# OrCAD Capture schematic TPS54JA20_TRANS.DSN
size E; title: TPS54JA20 2.7-V to 16-V Input, 12-A Synchronous Step-down; rev: 1.0; note: Datasheet:SNVSB02     EVM:NA; note: Synchronous Step Down Converter
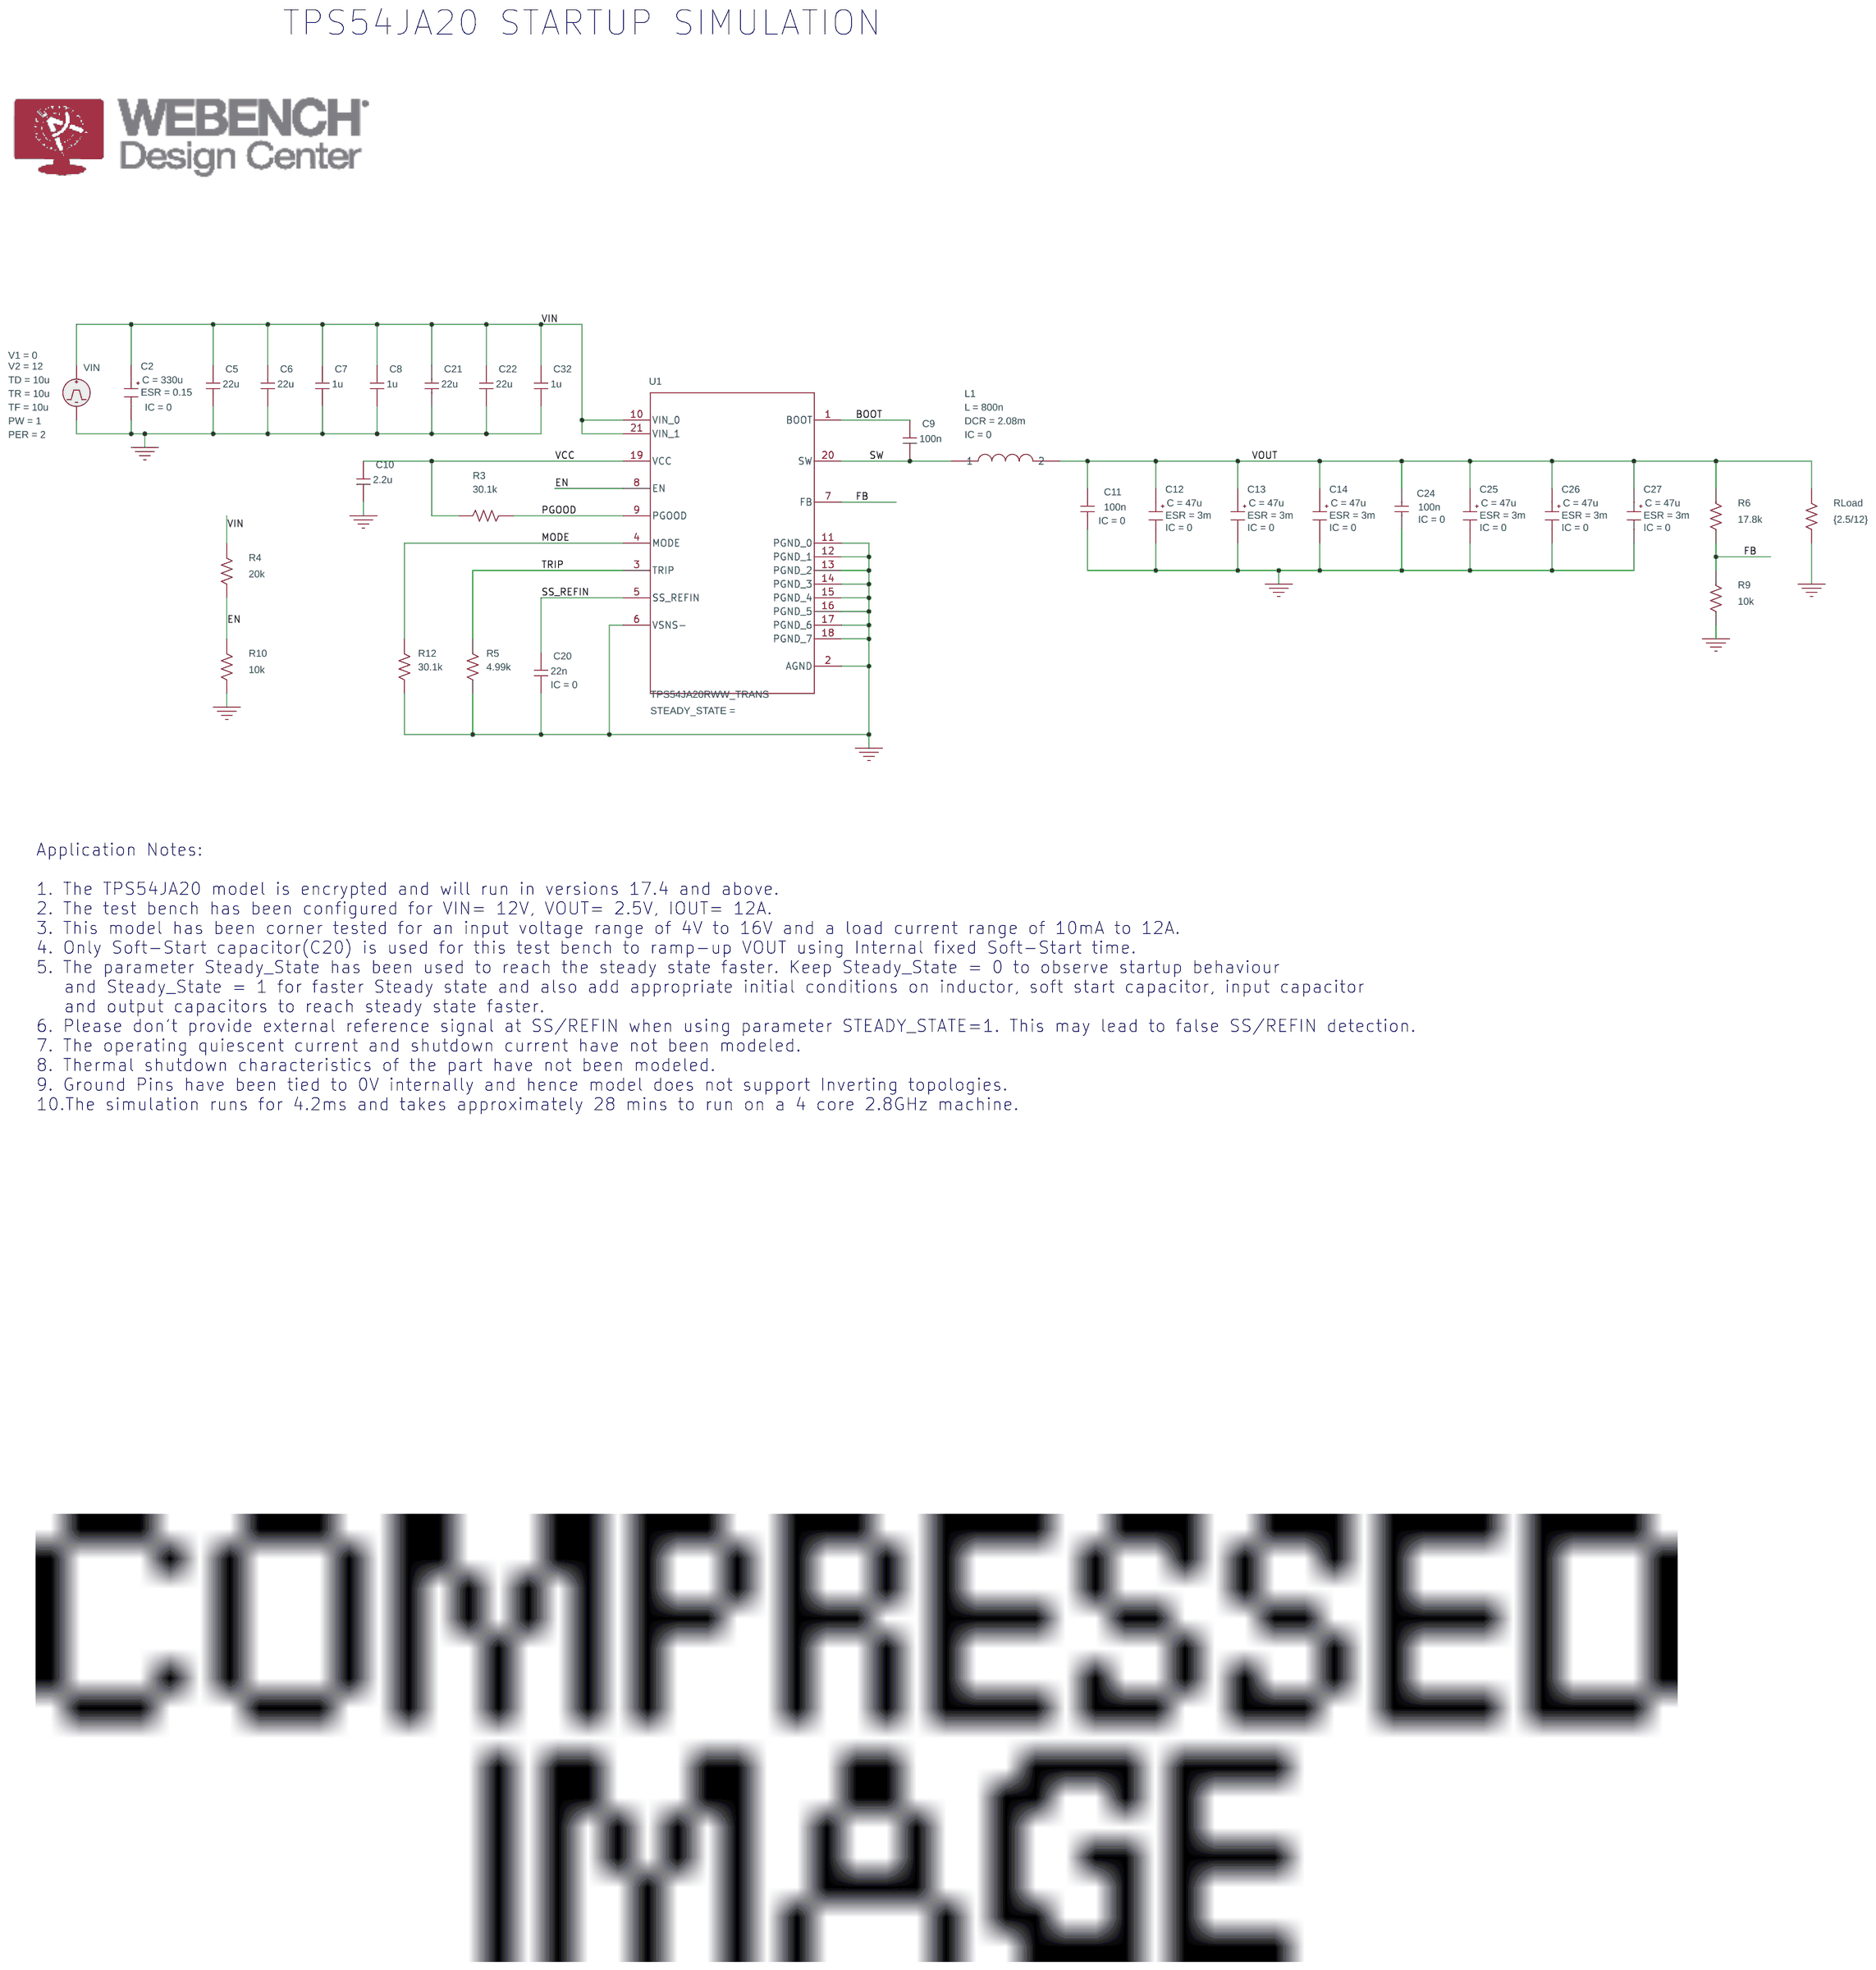
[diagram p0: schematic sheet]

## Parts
C2  CESR
C5  22u  [RAD/CK05]
C6  22u  [RAD/CK05]
C7  1u  [RAD/CK05]
C8  1u  [RAD/CK05]
C9  100n  [RAD/CK05]
C10  2.2u  [RAD/CK05]
C11  100n  [RAD/CK05]
C12  CESR
C13  CESR
C14  CESR
C20  22n  [RAD/CK05]
C21  22u  [RAD/CK05]
C22  22u  [RAD/CK05]
C24  100n  [RAD/CK05]
C25  CESR
C26  CESR
C27  CESR
C32  1u  [RAD/CK05]
L1  LDCR
R3  30.1k  [AX/RC05]
R4  20k  [AX/RC05]
R5  4.99k  [AX/RC05]
R6  17.8k  [AX/RC05]
R9  10k  [AX/RC05]
R10  10k  [AX/RC05]
R12  30.1k  [AX/RC05]
RLoad  {2.5/12}  [AX/RC05]
U1  TPS54JA20RWW_TRANS  [RWW0021A]
VIN  VPULSE

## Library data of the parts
C2 = CESR_0: C: 330u; ESR: 0.15; IC: 0; PSpiceTemplate: X^@REFDES %IN %OUT @MODEL PARAMS:  ?C|C=@C||C=100u|  ?ESR|ESR=@ESR||ESR=0.01| ?X|X=@X||X=2|  ?IC|IC=@IC||IC=2|; X: 1
C5-C10 C21 C22 C32 = c_0
C11 C20 C24 = c_0: IC: 0
C12-C14 C25-C27 = CESR_0: C: 47u; ESR: 3m; IC: 0; PSpiceTemplate: X^@REFDES %IN %OUT @MODEL PARAMS:  ?C|C=@C||C=100u|  ?ESR|ESR=@ESR||ESR=0.01| ?X|X=@X||X=2|  ?IC|IC=@IC||IC=2|; X: 1
L1 = LDCR: DCR: 2.08m; IC: 0; L: 800n
R3-R6 R9 R10 R12 RLoad = R
U1 = TPS54JA20RWW_TRANS
VIN = VPULSE: PER: 2; PW: 1; TD: 10u; TF: 10u; TR: 10u; V1: 0; V2: 12

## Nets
VCC: C10.1 R3.2 U1.19(VCC)
VIN: C2.1(IN) C5.1 C6.1 C7.1 C8.1 C21.1 C22.1 C32.1 R4.1 U1.10(VIN_0) U1.21(VIN_1) VIN.1(+)
0: C2.2(OUT) C5.2 C6.2 C7.2 C8.2 C10.2 C11.2 C12.2(OUT) C13.2(OUT) C14.2(OUT) C20.2 C21.2 C22.2 C24.2 C25.2(OUT) C26.2(OUT) C27.2(OUT) C32.2 R5.2 R9.2 R10.2 R12.2 RLoad.2 U1.2(AGND) U1.6(VSNS-) U1.11(PGND_0) U1.12(PGND_1) U1.13(PGND_2) U1.14(PGND_3) U1.15(PGND_4) U1.16(PGND_5) U1.17(PGND_6) U1.18(PGND_7) VIN.2(-)
BOOT: C9.1 U1.1(BOOT)
EN: R4.2 R10.1 U1.8(EN)
FB: R6.2 R9.1 U1.7(FB)
MODE: R12.1 U1.4(MODE)
PGOOD: R3.1 U1.9(PGOOD)
SS_REFIN: C20.1 U1.5(SS_REFIN)
SW: C9.2 L1.1 U1.20(SW)
TRIP: R5.1 U1.3(TRIP)
VOUT: C11.1 C12.1(IN) C13.1(IN) C14.1(IN) C24.1 C25.1(IN) C26.1(IN) C27.1(IN) L1.2 R6.1 RLoad.1

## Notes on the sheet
- TPS54JA20 STARTUP SIMULATION
- Application Notes:
  1. The TPS54JA20 model is encrypted and will run in versions 17.4 and above.
  2. The test bench has been configured for VIN= 12V, VOUT= 2.5V, IOUT= 12A.
  3. This model has been corner tested for an input voltage range of 4V to 16V and a load current range of 10mA to 12A.
  4. Only Soft-Start capacitor(C20) is used for this test bench to ramp-up VOUT using Internal fixed Soft-Start time.
  5. The parameter Steady_State has been used to reach the steady state faster. Keep Steady_State = 0 to observe startup behaviour
     and Steady_State = 1 for faster Steady state and also add appropriate initial conditions on inductor, soft start capacitor, input capacitor
     and output capacitors to reach steady state faster.
  6. Please don't provide external reference signal at SS/REFIN when using parameter STEADY_STATE=1. This may lead to false SS/REFIN detection.
  7. The operating quiescent current and shutdown current have not been modeled.
  8. Thermal shutdown characteristics of the part have not been modeled.
  9. Ground Pins have been tied to 0V internally and hence model does not support Inverting topologies.
  10.The simulation runs for 4.2ms and takes approximately 28 mins to run on a 4 core 2.8GHz machine.
